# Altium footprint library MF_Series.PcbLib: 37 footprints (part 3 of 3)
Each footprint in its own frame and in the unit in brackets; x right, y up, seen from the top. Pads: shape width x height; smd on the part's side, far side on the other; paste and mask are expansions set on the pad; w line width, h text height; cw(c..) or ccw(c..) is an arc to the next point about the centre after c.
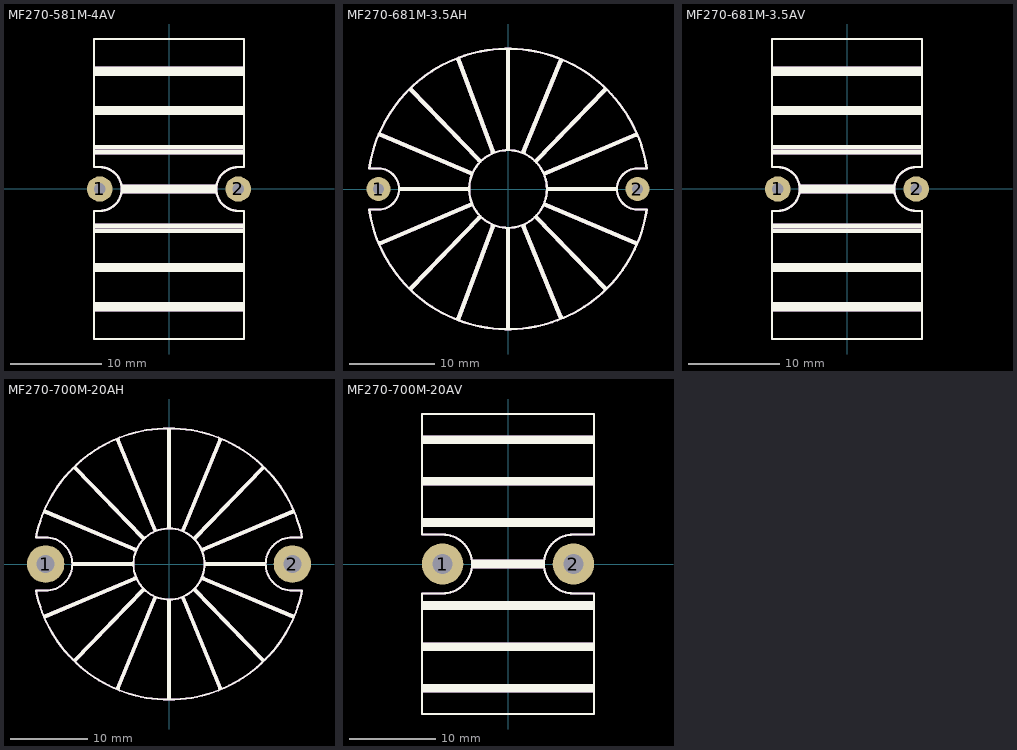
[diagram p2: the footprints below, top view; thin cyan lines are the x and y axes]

## MF270-581M-4AV [mil]
pads (2):
  round 110 hole 51: 1(-300,0) 2(300,0)
Top Overlay:
  lines w10: -325,-650 325,-650 325,-95 300,-95 cw(c300,0) 300,95 325,95 325,650 -325,650 -325,95 -300,95 cw(c-300,0) -300,-95 -325,-95 -325,-650
  lines w19.68: -320,-520 320,-520 ; -320,-500 320,-500 ; -320,-350 320,-350 ; -320,-330 320,-330 ; -320,-180 320,-180 ; -320,-160 320,-160 ; -320,160 320,160 ; -320,180 320,180 ; -320,330 320,330 ; -320,350 320,350 ; -320,500 320,500 ; -320,520 320,520 ; -200,-10 200,-10 ; -200,10 200,10
Mechanical 29:
  lines w10: -325,-650 325,-650 325,-95 300,-95 cw(c300,0) 300,95 325,95 325,650 -325,650 -325,95 -300,95 cw(c-300,0) -300,-95 -325,-95 -325,-650
  lines w19.68: -320,-520 320,-520 ; -320,-500 320,-500 ; -320,-350 320,-350 ; -320,-330 320,-330 ; -320,-180 320,-180 ; -320,-160 320,-160 ; -320,160 320,160 ; -320,180 320,180 ; -320,330 320,330 ; -320,350 320,350 ; -320,500 320,500 ; -320,520 320,520 ; -200,-10 200,-10 ; -200,10 200,10
  text "'.Designator'" at -1750,-64.83 h400

## MF270-681M-3.5AH [mil]
pads (2):
  round 110 hole 51: 1(-600,0) 2(600,0)
Top Overlay:
  circle w10: c0,0 r180
  lines w10: -643.01,-95.07 ccw(c0,0) 643.06,-94.71 ; -643.01,95.07 cw(c0,0) 642.96,95.44 ; -642.52,-95 -600,-95 ccw(c-600,0) -600,95 -642.52,95 ; 642.52,-95 600,-95 cw(c600,0) 600,95 642.52,95
  lines w19.68: -594.24,-251.8 -175.3,-74.28 ; -593.79,252.95 -173.05,74.68 ; -500,0 -185,0 ; -450,-460 -132.7,-132.43 ; -450,460 -132.7,132.43 ; -230,-600 -70.44,-171.87 ; -230,600 -70.44,171.87 ; 0,-640 0,-185 ; 0,185 0,640 ; 72.46,-173.99 243.97,-592.47 ; 72.46,173.99 243.97,592.47 ; 132.5,-132.5 450,-460 ; 132.5,132.5 450,460 ; 175.3,-74.28 590,-250 ; 175.3,74.28 594.24,251.8 ; 185,0 500,0
Mechanical 29:
  circle w10: c0,0 r180
  lines w10: -643.01,-95.07 ccw(c0,0) 643.06,-94.71 ; -643.01,95.07 cw(c0,0) 642.96,95.44 ; -642.52,-95 -600,-95 ccw(c-600,0) -600,95 -642.52,95 ; 642.52,-95 600,-95 cw(c600,0) 600,95 642.52,95
  lines w19.68: -594.24,-251.8 -175.3,-74.28 ; -593.79,252.95 -173.05,74.68 ; -500,0 -185,0 ; -450,-460 -132.7,-132.43 ; -450,460 -132.7,132.43 ; -230,-600 -70.44,-171.87 ; -230,600 -70.44,171.87 ; 0,-640 0,-185 ; 0,185 0,640 ; 72.46,-173.99 243.97,-592.47 ; 72.46,173.99 243.97,592.47 ; 132.5,-132.5 450,-460 ; 132.5,132.5 450,460 ; 175.3,-74.28 590,-250 ; 175.3,74.28 594.24,251.8 ; 185,0 500,0
  text "'.Designator'" at -290,145.17 h400

## MF270-681M-3.5AV [mil]
pads (2):
  round 110 hole 51: 1(-300,0) 2(300,0)
Top Overlay:
  lines w10: -325,-650 -325,-95 -300,-95 ccw(c-300,0) -300,95 -325,95 -325,650 325,650 325,95 300,95 ccw(c300,0) 300,-95 325,-95 325,-650 -325,-650
  lines w19.68: -320,-520 320,-520 ; -320,-500 320,-500 ; -320,-350 320,-350 ; -320,-330 320,-330 ; -320,-180 320,-180 ; -320,-160 320,-160 ; -320,160 320,160 ; -320,180 320,180 ; -320,330 320,330 ; -320,350 320,350 ; -320,500 320,500 ; -320,520 320,520 ; -200,-10 200,-10 ; -200,10 200,10
Mechanical 29:
  lines w10: -325,-650 -325,-95 -300,-95 ccw(c-300,0) -300,95 -325,95 -325,650 325,650 325,95 300,95 ccw(c300,0) 300,-95 325,-95 325,-650 -325,-650
  lines w19.68: -320,-520 320,-520 ; -320,-500 320,-500 ; -320,-350 320,-350 ; -320,-330 320,-330 ; -320,-180 320,-180 ; -320,-160 320,-160 ; -320,160 320,160 ; -320,180 320,180 ; -320,330 320,330 ; -320,350 320,350 ; -320,500 320,500 ; -320,520 320,520 ; -200,-10 200,-10 ; -200,10 200,10
  text "'.Designator'" at -1750,-64.83 h400

## MF270-700M-20AH [mil]
pads (2):
  round 190 hole 92: 1(-625,0) 2(625,0)
Top Overlay:
  circle w10: c0,0 r180
  lines w10: 674.08,135 625,135 ccw(c625,0) 625,-135 674.08,-135 cw(c0,0) -674.11,-135.01 -625,-135 ccw(c-625,0) -625,135 -674.08,135 cw(c0,0) 674.08,135.18
  lines w19.68: -628.31,-266.24 -175.3,-74.28 ; -628.31,266.24 -175.3,74.28 ; -485,0 -185,0 ; -474.96,-485.75 -132.5,-132.5 ; -474.96,485.75 -132.5,132.5 ; -259.04,-629.24 -72.46,-173.99 ; -259.04,629.24 -72.46,173.99 ; 0,-680 0,-185 ; 0,185 0,680 ; 72.46,-173.99 259.04,-629.24 ; 72.46,173.99 259.04,629.24 ; 132.5,-132.5 474.96,-485.75 ; 132.5,132.5 474.96,485.75 ; 175.3,-74.28 628.31,-266.24 ; 175.3,74.28 628.31,266.24 ; 185,0 485,0
Mechanical 29:
  circle w10: c0,0 r180
  lines w10: 674.08,135 625,135 ccw(c625,0) 625,-135 674.08,-135 cw(c0,0) -674.11,-135.01 -625,-135 ccw(c-625,0) -625,135 -674.08,135 cw(c0,0) 674.08,135.18
  lines w19.68: -628.31,-266.24 -175.3,-74.28 ; -628.31,266.24 -175.3,74.28 ; -485,0 -185,0 ; -474.96,-485.75 -132.5,-132.5 ; -474.96,485.75 -132.5,132.5 ; -259.04,-629.24 -72.46,-173.99 ; -259.04,629.24 -72.46,173.99 ; 0,-680 0,-185 ; 0,185 0,680 ; 72.46,-173.99 259.04,-629.24 ; 72.46,173.99 259.04,629.24 ; 132.5,-132.5 474.96,-485.75 ; 132.5,132.5 474.96,485.75 ; 175.3,-74.28 628.31,-266.24 ; 175.3,74.28 628.31,266.24 ; 185,0 485,0
  text "'.Designator'" at -290,145.17 h400

## MF270-700M-20AV [mil]
pads (2):
  round 190 hole 92: 1(-300,0) 2(300,0)
Top Overlay:
  lines w10: -393.5,-687.5 393.5,-687.5 393.5,-135 300,-135 cw(c300,0) 300,135 393.5,135 393.5,687.5 -393.5,687.5 -393.5,135 -300,135 cw(c-300,0) -300,-135 -393.5,-135 -393.5,-687.5
  lines w19.68: -385,-580 385,-580 ; -385,-560 385,-560 ; -385,-390 385,-390 ; -385,-370 385,-370 ; -385,-200 385,-200 ; -385,-180 385,-180 ; -385,180 385,180 ; -385,200 385,200 ; -385,370 385,370 ; -385,390 385,390 ; -385,560 385,560 ; -385,580 385,580 ; -160,-10 160,-10 ; -160,10 160,10
Mechanical 29:
  lines w10: -393.5,-687.5 393.5,-687.5 393.5,-135 300,-135 cw(c300,0) 300,135 393.5,135 393.5,687.5 -393.5,687.5 -393.5,135 -300,135 cw(c-300,0) -300,-135 -393.5,-135 -393.5,-687.5
  lines w19.68: -385,-580 385,-580 ; -385,-560 385,-560 ; -385,-390 385,-390 ; -385,-370 385,-370 ; -385,-200 385,-200 ; -385,-180 385,-180 ; -385,180 385,180 ; -385,200 385,200 ; -385,370 385,370 ; -385,390 385,390 ; -385,560 385,560 ; -385,580 385,580 ; -160,-10 160,-10 ; -160,10 160,10
  text "'.Designator'" at -1750,-64.83 h400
